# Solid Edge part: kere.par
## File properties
Author: Georg
Template: Iso Metric Part.par
Last saved by: Georg
Revision: 10
Application: Solid Edge
Accuracy: 0,990
Face Style: Model Default
Fill Style: Normal
Coef. of Thermal Exp: 0.0
Thermal Conductivity: 0.0
Specific Heat: 0.0
Modulus of Elasticity: 0.0
Poisson's Ratio: 0.0
Yield Stress: 0.0
Ultimate Stress: 0.0
Elongation: 0.0
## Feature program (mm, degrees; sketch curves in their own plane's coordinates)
lofted protrusion "unnamed LoftedProtrusion 1"
sketch used by "ExtrudedCutout_1" plane through (0, 0, 0) normal (0, 0, 1) x-axis (1, 0, 0)
extrude "ExtrudedCutout_1" cut finite 700 symmetric
lofted protrusion "unnamed LoftedProtrusion 2"
lofted protrusion "unnamed LoftedProtrusion 3"
mirror "unnamed Mirror 1" of "unnamed LoftedProtrusion 2" about plane through (0, 5551.072, -180) normal (-0.707107, 0, 0.707107)
lofted protrusion "unnamed LoftedProtrusion 4"
mirror "unnamed Mirror 2" of "unnamed Mirror 1" about plane through (0, 0, 0) normal (1, 0, 0)
lofted protrusion "unnamed LoftedProtrusion 5"
mirror "unnamed Mirror 3" of "unnamed LoftedProtrusion 3" about plane through (0, 5551.072, -180) normal (-0.707107, 0, 0.707107)
lofted protrusion "unnamed LoftedProtrusion 6"
mirror "unnamed Mirror 4" of "unnamed Mirror 3" about plane through (0, 0, 0) normal (1, 0, 0)
lofted protrusion "unnamed LoftedProtrusion 7"
sketch for "ExtrudedCutout_2" plane through (0, 0, -350) normal (0, 0, 1) x-axis (1, 0, 0)
  line (-200, 4600) -> (-200, 3600)
  line (-200, 3600) -> (200, 3600)
  line (200, 3600) -> (200, 4600)
  line (200, 4600) -> (-200, 4600)
extrude "ExtrudedCutout_2" cut finite 400 symmetric
sketch for "ExtrudedCutout_3" plane through (0, 4100, -150) normal (0, 0, -1) x-axis (0, -1, 0)
extrude "ExtrudedCutout_3" cut finite 15 along -normal
sketch for "ExtrudedCutout_4" plane through (-0.0122, 0, -121.051) normal (0, -1, 0) x-axis (1, 0, 0)
extrude "ExtrudedCutout_4" cut finite 160 along -normal
thicken "Thicken_3"  Distance1 = 5 mm
thicken "Thicken_4"  Distance1 = 5 mm
thicken "Thicken_5"  Distance1 = 5 mm
thicken "Thicken_6"  Distance1 = 5 mm
thicken "Thicken_7"  Distance1 = 5 mm
thicken "Thicken_8"  Distance1 = 5 mm
thicken "Thicken_9"  Distance1 = 5 mm
thicken "Thicken_10"  Distance1 = 5 mm
thicken "Thicken_11"  Distance1 = 5 mm
thicken "Thicken_12"  Distance1 = 5 mm
fillet "Round_1" radius 50
fillet "Round_2" radius 20
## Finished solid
Body 1: sheet body, 1 face, 12 edges, 12 vertices.
  Faces by surface: spline 1
  Edges by curve: curve on surface 12
Body 2: sheet body, 1 face, 10 edges, 10 vertices.
  Faces by surface: spline 1
  Edges by curve: curve on surface 10
Body 3: sheet body, 1 face, 6 edges, 6 vertices.
  Faces by surface: spline 1
  Edges by curve: curve on surface 6
Body 4: sheet body, 1 face, 9 edges, 9 vertices.
  Faces by surface: spline 1
  Edges by curve: curve on surface 9
Body 5: sheet body, 1 face, 4 edges, 4 vertices.
  Faces by surface: spline 1
  Edges by curve: curve on surface 4
Body 6: sheet body, 1 face, 4 edges, 4 vertices.
  Faces by surface: spline 1
  Edges by curve: curve on surface 4
Body 7: sheet body, 1 face, 15 edges, 15 vertices.
  Faces by surface: spline 1
  Edges by curve: curve on surface 15
Body 8: sheet body, 1 face, 16 edges, 16 vertices.
  Faces by surface: spline 1
  Edges by curve: curve on surface 16
Body 9: sheet body, 1 face, 12 edges, 12 vertices.
  Faces by surface: spline 1
  Edges by curve: curve on surface 12
Body 10: sheet body, 1 face, 10 edges, 10 vertices.
  Faces by surface: spline 1
  Edges by curve: curve on surface 10
Body 11: solid body, 151 faces, 425 edges, 293 vertices.
  Faces by surface: spline 115, plane 15, offset 10, cylinder 6, blend 4, swept 1
  Edges by curve: curve on surface 208, intersection 72, spline 58, circle 48, line 26, ellipse 13
Bounding box of the edges (mm; curved faces can reach further): 1461.352 x 7251.072 x 1013.839, from (-730.6763, 0, -463.1626) to (730.6763, 7251.072, 550.6763).
Cylindrical faces by radius (mm): R15 x1, R20 x4, R25 x1
Planar faces by outward normal: +x 2, +y 5, +z 1, -x 2, -y 3, -z 2
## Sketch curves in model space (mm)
spline (0, 3926.8223, -335.9102) -> (0, 3967.7402, -215.2426) -> (0, 4008.658, -94.5751)
spline (0, 3995.1792, -335.9102) -> (0, 3961.0008, -335.9102) -> (0, 3926.8223, -335.9102)
spline (0, 4010.5836, -290.6599) -> (0, 4002.8814, -313.285) -> (0, 3995.1792, -335.9102)
spline (0, 4044.1202, -265.9487) -> (0, 4027.3519, -278.3043) -> (0, 4010.5836, -290.6599)
spline (0, 4055.6734, -335.9102) -> (0, 4049.8968, -300.9294) -> (0, 4044.1202, -265.9487)
spline (0, 4131.0906, -335.9102) -> (0, 4093.382, -335.9102) -> (0, 4055.6734, -335.9102)
spline (0, 4103.3307, -222.6239) -> (0, 4117.2107, -279.267) -> (0, 4131.0906, -335.9102)
spline (0, 4186.9314, -161.3274) -> (0, 4145.1311, -191.9756) -> (0, 4103.3307, -222.6239)
spline (0, 4104.4539, -161.3274) -> (0, 4145.6927, -161.3274) -> (0, 4186.9314, -161.3274)
spline (0, 4034.8133, -219.2542) -> (0, 4069.6336, -190.2908) -> (0, 4104.4539, -161.3274)
spline (0, 4077.0149, -94.5751) -> (0, 4055.9141, -156.9147) -> (0, 4034.8133, -219.2542)
spline (0, 4008.658, -94.5751) -> (0, 4042.8365, -94.5751) -> (0, 4077.0149, -94.5751)
spline (0, 3702.0149, -335.9102) -> (0, 3743.013, -215.2426) -> (0, 3784.011, -94.5751)
spline (0, 3769.0881, -335.9102) -> (0, 3735.5515, -335.9102) -> (0, 3702.0149, -335.9102)
spline (0, 3851.8865, -239.9538) -> (0, 3802.5724, -239.6061) -> (0, 3769.0881, -335.9102)
spline (0, 3819.3127, -335.9102) -> (0, 3835.5996, -287.932) -> (0, 3851.8865, -239.9538)
spline (0, 3886.5463, -335.9102) -> (0, 3852.9295, -335.9102) -> (0, 3819.3127, -335.9102)
spline (0, 3924.0945, -225.0308) -> (0, 3905.3204, -280.4705) -> (0, 3886.5463, -335.9102)
spline (0, 3925.8596, -174.0039) -> (0, 3930.3926, -195.1247) -> (0, 3924.0945, -225.0308)
spline (0, 3820.9173, -183.6316) -> (0, 3874.6842, -158.4436) -> (0, 3925.8596, -174.0039)
spline (0, 3851.0842, -94.5751) -> (0, 3836.0008, -139.1034) -> (0, 3820.9173, -183.6316)
spline (0, 3784.011, -94.5751) -> (0, 3817.5476, -94.5751) -> (0, 3851.0842, -94.5751)
spline (0, 3669.762, -46.1156) -> (0, 3673.3323, -41.763) -> (0, 3676.6619, -34.8832)
spline (0, 3627.2395, -36.1669) -> (0, 3651.0862, -46.6947) -> (0, 3669.762, -46.1156)
spline (0, 3590.3332, -45.3133) -> (0, 3609.348, -35.7207) -> (0, 3627.2395, -36.1669)
spline (0, 3571.0778, -73.715) -> (0, 3578.9003, -57.709) -> (0, 3590.3332, -45.3133)
spline (0, 3568.8313, -80.7754) -> (0, 3569.9546, -77.0045) -> (0, 3571.0778, -73.715)
spline (0, 3594.3448, -80.7754) -> (0, 3581.5881, -80.7754) -> (0, 3568.8313, -80.7754)
spline (0, 3700.2498, -42.2645) -> (0, 3656.3685, -81.1987) -> (0, 3594.3448, -80.7754)
spline (0, 3702.6567, -34.8832) -> (0, 3701.3329, -38.8747) -> (0, 3700.2498, -42.2645)
spline (0, 3676.6619, -34.8832) -> (0, 3689.6593, -34.8832) -> (0, 3702.6567, -34.8832)
spline (0, 3601.4051, -268.6765) -> (0, 3629.3692, -153.4942) -> (0, 3531.6041, -215.724)
spline (0, 3531.6041, -215.724) -> (0, 3535.1253, -277.8679) -> (0, 3601.4051, -268.6765)
spline (0, 3614.4026, -325.1592) -> (0, 3484.331, -329.9181) -> (0, 3457.3101, -215.4031)
spline (0, 3669.9225, -282.9577) -> (0, 3644.3288, -307.1273) -> (0, 3614.4026, -325.1592)
spline (0, 3706.0264, -122.656) -> (0, 3710.5757, -204.6926) -> (0, 3669.9225, -282.9577)
spline (0, 3457.3101, -215.4031) -> (0, 3570.4367, -98.1246) -> (0, 3706.0264, -122.656)
spline (0, 3199.4475, -335.9102) -> (0, 3229.0528, -248.6188) -> (0, 3258.658, -161.3274)
spline (0, 3266.5207, -335.9102) -> (0, 3232.9841, -335.9102) -> (0, 3199.4475, -335.9102)
spline (0, 3325.8917, -161.3274) -> (0, 3296.2062, -248.6188) -> (0, 3266.5207, -335.9102)
spline (0, 3258.658, -161.3274) -> (0, 3292.2748, -161.3274) -> (0, 3325.8917, -161.3274)
spline (0, 3265.7184, -140.6278) -> (0, 3273.581, -117.6014) -> (0, 3281.4436, -94.5751)
spline (0, 3332.952, -140.6278) -> (0, 3299.3352, -140.6278) -> (0, 3265.7184, -140.6278)
spline (0, 3348.5168, -94.5751) -> (0, 3340.7344, -117.6014) -> (0, 3332.952, -140.6278)
spline (0, 3281.4436, -94.5751) -> (0, 3314.9802, -94.5751) -> (0, 3348.5168, -94.5751)
spline (0, 3131.572, -129.0745) -> (0, 3170.9655, -111.8248) -> (0, 3210.3589, -94.5751)
spline (0, 3120.6606, -161.3274) -> (0, 3126.1163, -145.2009) -> (0, 3131.572, -129.0745)
spline (0, 3095.9494, -161.3274) -> (0, 3108.305, -161.3274) -> (0, 3120.6606, -161.3274)
spline (0, 3079.4218, -210.2683) -> (0, 3087.6856, -185.7978) -> (0, 3095.9494, -161.3274)
spline (0, 3103.9725, -210.2683) -> (0, 3091.6972, -210.2683) -> (0, 3079.4218, -210.2683)
spline (0, 3085.3589, -333.5032) -> (0, 3082.7382, -272.8359) -> (0, 3103.9725, -210.2683)
spline (0, 3168.3178, -334.466) -> (0, 3116.9474, -339.895) -> (0, 3085.3589, -333.5032)
spline (0, 3179.0688, -288.4134) -> (0, 3173.6933, -311.4397) -> (0, 3168.3178, -334.466)
spline (0, 3147.1368, -286.9692) -> (0, 3156.0556, -292.5751) -> (0, 3179.0688, -288.4134)
spline (0, 3150.0252, -272.2067) -> (0, 3147.4979, -281.5737) -> (0, 3147.1368, -286.9692)
spline (0, 3171.0457, -210.2683) -> (0, 3160.5354, -241.2375) -> (0, 3150.0252, -272.2067)
spline (0, 3207.952, -210.2683) -> (0, 3189.4988, -210.2683) -> (0, 3171.0457, -210.2683)
spline (0, 3224.4796, -161.3274) -> (0, 3216.2158, -185.7978) -> (0, 3207.952, -210.2683)
spline (0, 3187.7338, -161.3274) -> (0, 3206.1067, -161.3274) -> (0, 3224.4796, -161.3274)
spline (0, 3210.3589, -94.5751) -> (0, 3199.0463, -127.9513) -> (0, 3187.7338, -161.3274)
spline (0, 3016.0393, -308.6316) -> (0, 2897.9058, -338.7351) -> (0, 2846.7517, -286.9692)
spline (0, 3035.1343, -279.267) -> (0, 3027.8132, -294.19) -> (0, 3016.0393, -308.6316)
spline (0, 2971.2703, -222.303) -> (0, 3021.1323, -234.7767) -> (0, 3035.1343, -279.267)
spline (0, 2949.608, -196.95) -> (0, 2945.1758, -216.749) -> (0, 2971.2703, -222.303)
spline (0, 2984.7492, -198.2337) -> (0, 2967.4193, -192.9384) -> (0, 2949.608, -196.95)
spline (0, 2988.9212, -210.2683) -> (0, 2988.0386, -203.1679) -> (0, 2984.7492, -198.2337)
spline (0, 3054.5502, -204.1708) -> (0, 3021.7357, -207.2195) -> (0, 2988.9212, -210.2683)
spline (0, 2933.7222, -163.5738) -> (0, 3028.1404, -162.5528) -> (0, 3054.5502, -204.1708)
spline (0, 2899.7042, -182.1875) -> (0, 2915.3894, -171.3763) -> (0, 2933.7222, -163.5738)
spline (0, 2879.486, -239.9538) -> (0, 2880.9249, -208.3728) -> (0, 2899.7042, -182.1875)
spline (0, 2896.3345, -257.4442) -> (0, 2886.2254, -250.5644) -> (0, 2879.486, -239.9538)
spline (0, 2967.4193, -275.5764) -> (0, 2928.5583, -266.2742) -> (0, 2896.3345, -257.4442)
spline (0, 2961.8031, -297.2388) -> (0, 2971.3301, -285.9346) -> (0, 2967.4193, -275.5764)
spline (0, 2920.8852, -297.8806) -> (0, 2940.2879, -302.9994) -> (0, 2961.8031, -297.2388)
spline (0, 2915.1086, -280.8717) -> (0, 2916.5528, -291.1212) -> (0, 2920.8852, -297.8806)
spline (0, 2846.7517, -286.9692) -> (0, 2880.9302, -283.9204) -> (0, 2915.1086, -280.8717)
spline (0, 2711.9635, -233.2144) -> (0, 2745.1792, -233.2144) -> (0, 2778.3949, -233.2144)
spline (0, 2778.3949, -233.2144) -> (0, 2755.5871, -197.3269) -> (0, 2711.9635, -233.2144)
spline (0, 2638.4719, -248.9397) -> (0, 2774.0023, -157.542) -> (0, 2835.5194, -265.3068)
spline (0, 2634.6208, -299.0039) -> (0, 2632.6351, -275.8973) -> (0, 2638.4719, -248.9397)
spline (0, 2657.0855, -330.1335) -> (0, 2643.1453, -317.457) -> (0, 2634.6208, -299.0039)
spline (0, 2773.7415, -328.3685) -> (0, 2713.4301, -339.8755) -> (0, 2657.0855, -330.1335)
spline (0, 2823.1638, -290.4994) -> (0, 2798.7535, -313.2248) -> (0, 2773.7415, -328.3685)
spline (0, 2759.2999, -284.4018) -> (0, 2791.2318, -287.4506) -> (0, 2823.1638, -290.4994)
spline (0, 2700.8917, -265.3068) -> (0, 2715.448, -299.6276) -> (0, 2759.2999, -284.4018)
spline (0, 2835.5194, -265.3068) -> (0, 2768.2055, -265.3068) -> (0, 2700.8917, -265.3068)
spline (0, 2378.6837, -335.9102) -> (0, 2419.6015, -215.2426) -> (0, 2460.5194, -94.5751)
spline (0, 2581.6683, -335.9102) -> (0, 2480.176, -335.9102) -> (0, 2378.6837, -335.9102)
spline (0, 2600.2819, -281.353) -> (0, 2590.9751, -308.6316) -> (0, 2581.6683, -335.9102)
spline (0, 2471.5913, -281.353) -> (0, 2535.9366, -281.353) -> (0, 2600.2819, -281.353)
spline (0, 2487.7979, -233.6958) -> (0, 2479.6946, -257.5244) -> (0, 2471.5913, -281.353)
spline (0, 2603.8121, -233.6958) -> (0, 2545.805, -233.6958) -> (0, 2487.7979, -233.6958)
spline (0, 2620.6606, -184.2735) -> (0, 2612.2363, -208.9846) -> (0, 2603.8121, -233.6958)
spline (0, 2504.6465, -184.2735) -> (0, 2562.6535, -184.2735) -> (0, 2620.6606, -184.2735)
spline (0, 2517.4834, -146.2439) -> (0, 2511.065, -165.2587) -> (0, 2504.6465, -184.2735)
spline (0, 2642.6439, -146.2439) -> (0, 2580.0637, -146.2439) -> (0, 2517.4834, -146.2439)
spline (0, 2660.1343, -94.5751) -> (0, 2651.3891, -120.4095) -> (0, 2642.6439, -146.2439)
spline (0, 2460.5194, -94.5751) -> (0, 2560.3268, -94.5751) -> (0, 2660.1343, -94.5751)
line (200, 3600, -350) -> (200, 4600, -350)
line (200, 4600, -350) -> (-200, 4600, -350)
line (-200, 4600, -350) -> (-200, 3600, -350)
line (-200, 3600, -350) -> (200, 3600, -350)
ellipse centre (0, 1917.2017, 0) radii 650, 340
line (0, 7251.072, 447.9853) -> (2.5275, 7251.072, 438.2355)
arc centre (0.5915, 7251.072, 437.7336) radius 2 from (2.5275, 7251.072, 438.2355) through (2.5763, 7251.072, 437.9798) to (2.5914, 7251.072, 437.7199)
ellipse centre (0, 7251.072, 437.9853) radii 10, 2.5924 from (-2.5914, 7251.072, 437.7199) through (0.1539, 7251.072, 428.003) to (2.5914, 7251.072, 437.7199)
arc centre (-0.5915, 7251.072, 437.7337) radius 2 from (-2.5275, 7251.072, 438.2355) through (-2.5763, 7251.072, 437.9798) to (-2.5914, 7251.072, 437.7199)
line (-2.5275, 7251.072, 438.2355) -> (0, 7251.072, 447.9853)
arc centre (-0.0098, 6451.072, 435.5623) radius 20 from (19.3931, 6451.072, 440.413) through (19.8501, 6451.072, 437.9258) to (19.9896, 6451.072, 435.4007)
ellipse centre (0, 6451.072, 437.9853) radii 80, 20 from (-19.9896, 6451.072, 435.4007) through (1.1828, 6451.072, 358.1253) to (19.9896, 6451.072, 435.4007)
arc centre (0.0098, 6451.072, 435.5623) radius 20 from (-19.3931, 6451.072, 440.413) through (-19.8501, 6451.072, 437.9258) to (-19.9896, 6451.072, 435.4007)
line (-19.3931, 6451.072, 440.413) -> (0, 6451.072, 517.9853)
line (0, 6451.072, 517.9853) -> (19.3931, 6451.072, 440.413)
line (0, 5201.072, -80) -> (89.3675, 5548.6122, -80)
arc centre (69.9976, 5553.593, -80) radius 20 from (89.3675, 5548.6122, -80) through (89.8418, 5551.1014, -80) to (89.9976, 5553.6306, -80)
ellipse centre (0, 5551.072, -80) radii 350.0063, 90 from (89.9976, 5553.6306, -80) through (-2.6546, 5900.926, -80) to (-89.9976, 5553.6306, -80)
arc centre (-69.9976, 5553.593, -80) radius 20 from (-89.3675, 5548.6122, -80) through (-89.8418, 5551.1014, -80) to (-89.9976, 5553.6306, -80)
line (-89.3675, 5548.6122, -80) -> (0, 5201.072, -80)
arc centre (300, 3551.072, -23.1228) radius 100 from (400, 3551.072, -23.1228) through (368.6242, 3551.072, 49.6146) to (300, 3551.072, 76.8772)
line (400, 3551.072, -23.1228) -> (400, 3551.072, -193.1228)
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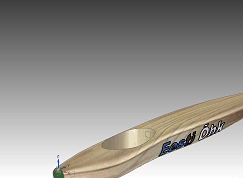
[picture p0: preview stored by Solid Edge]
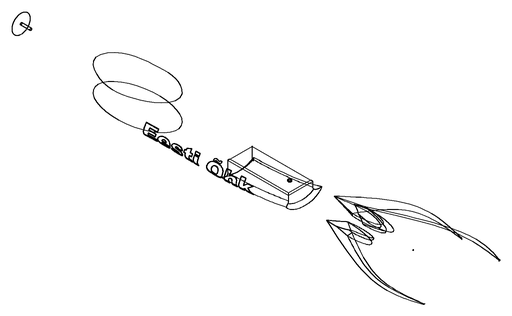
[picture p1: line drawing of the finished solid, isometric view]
